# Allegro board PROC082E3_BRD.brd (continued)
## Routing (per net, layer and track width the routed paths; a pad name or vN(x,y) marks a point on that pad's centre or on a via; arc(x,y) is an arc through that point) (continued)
VCC_1V1: length 15.3
  L6_SIG2 w0.381: TP33.1 11.96,24.65 v1(18.99,17.62)
  BOTTOM w0.254: R243.1 19.18,17.81 v1(18.99,17.62)
  vias: v1(7.32,34.16) v1(7.32,33.27) v1(7.32,32.38) v1(7.57,29.54) v1(7.57,28.65) v1(8.2,34.16) v1(8.2,33.27) v1(8.2,32.38) v1(8.46,29.54) v1(8.46,28.65) v1(26.83,142.2) v1(26.86,142.88) v1(27.75,142.88) v1(27.72,142.2) v1(28.64,142.88) v1(28.61,142.2) v1(29.45,142.88) v1(29.42,142.2)
VCC_1V1_CBOOT: length 2.1
  TOP w0.254: v1(16,25.25) 15.84,25.09 C484.1
  BOTTOM w0.203: v1(16,25.25) 16.25,25 U33.13
VCC_1V1_COMP: length 2.5
  BOTTOM w0.254: C502.1 R244.1 U33.7
VCC_1V1_EN: length 1.9
  TOP w0.254: v1(17.45,25.15) 17.77,24.82 R197.2
  BOTTOM w0.203: v1(17.45,25.15) 17.25,24.94 U33.15
VCC_1V1_FB: length 3.1
  BOTTOM w0.254: U33.6 17.25,20.57 17.81,20.02 R239.1 R243.2
VCC_1V1_PG: length 1.9
  TOP w0.254: v1(16.75,25.17) 17.1,25.53 R245.1
  BOTTOM w0.203: U33.14 v1(16.75,25.17)
VCC_1V1_SW: length 1.4
  TOP w0.254: C484.2 14.86,24.97 14.63,25.2 v1(14.63,25.65)
VCC_1V8: length 12.8
  TOP w0.254: v1(17.81,72.7) 17.71,72.8 C473.1
  TOP w0.381: v1(37.9,161.59) 37.52,161.21 FL76.2 ; FL80.1 37.72,168.28 v1(37.82,168.17) ; FL78.2 v1(28.46,161.08)
  BOTTOM w0.254: v1(30.71,88.24) 30.81,88.24 31.06,88.49 U19.3
  BOTTOM w0.305: U22.2 18.21,74.45 18.42,74.24 C474.1 18.42,73.09 18.03,72.7 v1(17.81,72.7) ; U22.6 16.21,75.14 C243.1 v1(15.52,73.69)
  BOTTOM w0.381: R228.1 30.05,159.47 v1(30.05,159.31) ; R234.1 v1(33.58,160.24) ; R223.1 v1(34.74,170.38)
  vias: v1(22.13,138.37) v1(23.28,138.37) v1(23.96,91.58) v1(23.96,90.56) v1(23.96,89.54) v1(23.96,88.53) v1(24.98,91.58) v1(24.98,90.56) v1(24.98,89.54) v1(24.98,88.53)
VCC_1V8_EN: length 1.3
  BOTTOM w0.254: U19.1 R145.1
VCC_1V8_SW: length 6.3
  BOTTOM w0.229: 31.56,90.84 U19.5
  BOTTOM w0.381: 31.56,91.11 31.56,90.84
  BOTTOM w0.635: L29.1 31.56,91.11
VCC_3V3:
  vias: v1(41.64,40.22) v1(41.67,41.56) v1(41.67,40.88) v1(42.48,41.59) v1(42.48,40.9) v1(42.45,40.24) v1(44.99,92.95) v1(44.99,91.93) v1(46.01,92.95) v1(46.01,91.93) v1(47.47,92.85)
VCC_12V: length 46.5
  TOP w0.254: v1(73.44,30.99) 75.63,30.99 TP56.1
  TOP w0.305: R258.1 53.84,7.3 C526.1
  TOP w0.381: v1(54.53,9.65) C526.1
  L03_SIG1 w0.381: v1(54.53,9.65) 54.53,12.27 50.67,16.13 v1(50.67,17.65)
  L6_SIG2 w0.381: 41.66,17.91 41.27,17.53 34.47,17.53 v1(33.6,16.66)
  BOTTOM w0.203: U4.9 74.04,164.95 73.86,165.13
  BOTTOM w0.305: R253.1 v1(33.6,16.66) ; U27.9 73.83,28.81 73.53,29.11 ; U26.9 73.77,47.66 73.53,47.9 ; U28.4 42.43,21.36 42.59,21.21 C344.1 ; 76.56,166.7 76.72,166.53 U4.13 ; U7.9 9.25,139.08 v1(9.51,138.82) ; U12.9 9.15,118.15 9.41,117.89 9.89,117.89 ; U18.9 74.06,86.42 73.84,86.64 ; U3.9 9.79,162.55 ; U8.9 74.09,145.32 73.69,145.72 ; 73.46,67.36 73.71,67.11 U23.9 ; 9.41,96.22 9.15,96.48 U16.9 ; U17.9 73.9,105.73 73.63,105.99 ; U13.9 73.65,125.28 73.41,125.53
  vias: v1(9.39,94.88) v1(9.41,94.19) v1(9.51,160.26) v1(9.51,137.8) v1(9.51,136.79) v1(9.89,116.88) v1(9.89,115.86) v1(10.53,161.27) v1(10.53,160.26) v1(10.53,138.82) v1(10.53,137.8) v1(10.53,136.79) v1(10.91,116.88) v1(10.91,115.86) v1(11.54,137.8) v1(11.54,136.79) v1(42.42,20.19) v1(43.31,20.19) v1(43.94,21.08) v1(44.2,20.19) v1(45.09,20.19) v1(46.23,21.34) v1(46.23,20.45) v1(46.23,19.56) v1(46.23,18.67) v1(47.12,21.34) v1(47.12,20.45) v1(47.12,19.56) v1(47.12,18.67) v1(48.01,21.34) v1(48.01,20.45) v1(48.01,19.56) v1(48.01,18.67) v1(48.9,21.34) v1(48.9,20.45) v1(48.9,19.56) v1(48.9,18.67) v1(49.78,21.34) v1(49.78,20.45) v1(49.78,19.56) v1(49.78,18.67) v1(50.67,21.34) v1(50.67,20.45) v1(50.67,19.56) v1(50.67,18.67) v1(71.41,69.29) v1(71.41,68.28) v1(71.41,67.26) v1(71.81,51.09) v1(71.81,50.07) v1(71.96,167.82) v1(71.96,167.06) v1(71.96,166.3) v1(71.96,165.53) v1(71.96,148.31) v1(71.96,147.55) v1(71.96,146.79) v1(71.96,146.03) v1(71.99,128.73) v1(71.99,127.97) v1(71.99,127.2) v1(71.99,126.44) v1(72.04,109.26) v1(72.04,108.5) v1(72.04,107.74) v1(72.04,106.97) v1(72.42,88.6) v1(72.42,87.58) v1(72.42,86.56) v1(72.42,69.29) v1(72.42,68.28) v1(72.42,67.26) v1(72.42,30.99) v1(72.42,29.97) v1(72.83,51.09) v1(72.83,50.07) v1(72.98,167.82) v1(72.98,167.06) v1(72.98,166.3) v1(72.98,165.53) v1(72.98,148.31) v1(72.98,147.55) v1(72.98,146.79) v1(72.98,146.03) v1(73.01,128.73) v1(73.01,127.97) v1(73.01,127.2) v1(73.01,126.44) v1(73.06,109.26) v1(73.06,108.5) v1(73.06,107.74) v1(73.06,106.97) v1(73.06,88.6) v1(73.06,87.58) v1(73.06,86.56) v1(73.44,69.29) v1(73.44,68.28) v1(73.44,29.97) v1(73.69,88.6) v1(73.69,87.58)
VCC_12V/20V_HDR:
  vias: v1(21.59,11.81) v1(21.59,10.79) v1(21.59,9.78) v1(21.59,6.99) v1(21.59,5.97) v1(22.61,11.81) v1(22.61,10.79) v1(22.61,9.78) v1(22.61,6.99) v1(22.61,5.97) v1(23.62,11.81) v1(23.62,10.79) v1(23.62,9.78) v1(23.62,6.99) v1(23.62,5.97)
VCC_12V_EXP_CONN:
  vias: v1(53.85,23.88) v1(54.74,23.88) v1(55.63,24.38) v1(55.63,23.62) v1(56.13,25.15) v1(56.26,24.38) v1(56.39,23.62) v1(56.77,25.15) v1(56.9,24.38) v1(57.15,23.62) v1(57.66,24.26) v1(58.04,23.62) v1(58.42,24.26) v1(59.01,80.15) v1(59.01,79.26) v1(59.01,78.37) v1(59.01,77.47) v1(59.44,76.71) v1(59.9,80.15) v1(59.9,79.26) v1(59.9,78.37) v1(59.9,77.48) v1(60.33,76.71) v1(71.25,11.68) v1(71.25,10.79) v1(71.25,9.91) v1(71.25,9.02) v1(72.14,11.68) v1(72.14,10.79) v1(72.14,9.91) v1(72.14,9.02) v1(73.03,11.68) v1(73.03,10.79) v1(73.03,9.91) v1(73.03,9.02) v1(73.91,11.68) v1(73.91,10.79) v1(73.91,9.91) v1(73.91,9.02) v1(74.8,11.68) v1(74.8,10.79) v1(74.8,9.91) v1(74.8,9.02) v1(75.69,11.68) v1(75.69,10.79) v1(75.69,9.91) v1(75.69,9.02) v1(76.58,11.68) v1(76.58,10.79) v1(76.58,9.91) v1(76.58,9.02) v1(77.47,11.68) v1(78.36,11.68)
VCC_CSI_IO: length 220.2
  TOP w0.381: v1(39.7,117.88) 39.7,116.18 39.22,115.7 C195.1 38.67,115.17 v1(38.28,115.56) 36.78,114.06 36.78,103.86 35.43,102.51 35.43,94.46 36.8,93.09 v1(36.8,89.08) 38.51,89.08 40.34,90.92 v1(41.07,90.92) v1(42.45,90.92) ; R197.1 18.75,24.35 19.13,24.72 v1(19.13,25.63) ; C309.1 22.8,54.39 v1(23.96,54.39) ; R17.1 25.9,122.58 v1(26.6,121.88) ; v1(26.85,31.62) 26.74,31.51 R209.1 ; R206.1 v1(47.5,105.83) ; 51.44,52.58 51.44,42.92 52.28,42.07 R46.1 R47.1 ; R212.1 v1(16.17,33.46)
  L03_SIG1 w0.381: 20.36,51.01 19.24,51.01 18.49,51.76 18.49,58.91 23.27,63.69 23.27,68.28 v1(22.1,69.45) ; 20.36,51.01 20.93,50.44 v1(20.93,47.09) 20.93,46.23 19.84,45.14 19.84,37.13 ; 20.36,51.01 20.36,51.54 23.2,54.39 v1(23.96,54.39) 24.54,54.97 v1(24.54,57.24) ; v1(39.7,117.88) 39.7,116.13 41.2,114.63 41.2,112.93 41.86,112.27 42.47,112.27 42.98,111.76 46.25,111.76 46.96,111.06 46.96,106.37 v1(47.5,105.83) ; 19.84,37.13 20.63,36.33 20.63,33.95 22.57,32 26.47,32 v1(26.85,31.62) ; 19.84,37.13 v1(16.17,33.46) 16.17,28.59 v1(19.13,25.63) ; v1(26.6,121.88) 27.44,121.04 36.68,121.04 37.57,121.93 37.57,126.15 36.97,126.75 v1(36.45,126.75) ; v1(10.3,94.19) 11.47,93.02 v1(15.11,93.02)
  BOTTOM w0.254: R145.2 35.44,87.71 v1(36.8,89.08)
  BOTTOM w0.305: U9.16 37.88,115.16 v1(38.28,115.56) ; U24.16 38.83,57.8 38.23,57.21 C302.1 v1(38.94,56.59) ; U25.16 21.67,54.94 22.22,54.39 C310.1
  BOTTOM w0.381: R170.2 22.08,68.66 R172.2 v1(22.1,69.45) ; v1(6.36,74.59) 6.73,74.59 7.11,74.97 FL60.1 v1(6.35,75.44) ; R149.1 v1(10.3,94.19) ; R180.2 v1(41.13,55.11) ; v1(38.28,115.56) 38.34,115.62 C191.1 ; v1(23.96,54.39) C310.1 ; v1(36.45,126.75) 37.53,127.82 R87.2 R86.2 39.86,128.17 42.73,128.17 42.91,128.35 44.78,128.35 45.82,127.31 45.82,119.59 44.11,117.88 v1(39.7,117.88) R99.2 ; U20.8 C241.1 v1(7.94,85.74) ; v1(15.11,93.02) 14.68,93.45 R146.1 ; v1(13.19,84.05) 12.79,84.05 R153.1 ; R176.2 R179.2 v1(51.14,56.83) ; v1(6.78,89.1) 6.78,89.94 7.38,90.54 R151.1 ; R178.2 v1(24.54,57.24)
  vias: v1(41.01,89.91) v1(41.83,91.89)
VDD1V8_P_HUB1: length 2.5
  BOTTOM w0.229: 25.07,110.92 25.65,110.92 25.82,111.09 U9.44
  BOTTOM w0.381: 25.07,110.92 24.84,110.68 C206.1 v1(24.84,109.62)
VDD1V8_P_HUB2: length 3.6
  TOP w0.381: v1(33.78,71.43) 33.72,71.38 C83.1
  BOTTOM w0.305: C85.1 34.77,70.84 35.08,70.54 U24.44
  BOTTOM w0.381: C85.1 v1(33.78,71.43)
VDD1V8_P_HUB3: length 4.5
  TOP w0.381: C109.1 8.02,49.56 v1(8.06,49.6) 8.08,49.58 C91.1
  BOTTOM w0.305: U25.44 9.85,50.64 9.63,50.42 9.25,50.42
  BOTTOM w0.381: 9.25,50.42 8.86,50.04 8.86,49.61 8.87,49.6 ; C89.1 8.87,49.6 ; 8.87,49.6 v1(8.06,49.6)
VDD11_CSI_HUB1: length 13
  TOP w0.254: 22.08,118.74 C463.1
  TOP w0.381: C459.1 23.12,113.15 v1(23.01,113.26) 22.95,113.32 22.95,114.17 C466.1 ; v1(25.59,110.09) 26.27,110.09 C460.1 C465.1 ; C462.1 23.18,118.75 22.65,118.75 v1(22.64,118.74) 22.08,118.74
  BOTTOM w0.229: U9.43 26.32,110.81 26.26,110.74 ; U9.30 32.82,110.5
  BOTTOM w0.305: 23.85,113.21 24.4,112.66 U9.46 ; C186.1 23.94,118.74 24.36,119.16 U9.59
  BOTTOM w0.381: 26.26,110.74 26.26,110.11 C205.1 v1(25.59,110.09) ; 23.85,113.21 23.85,113.21 C196.1 23.64,113.26 v1(23.01,113.26) ; v1(22.64,118.74) C186.1
  vias: v1(21.28,147.71) v1(21.3,146.99) v1(22.12,147.71) v1(22.14,146.99) v1(32.98,107.98) v1(33.1,109.35)
VDD11_CSI_HUB2: length 21.7
  TOP w0.381: v1(37.6,71.86) 37.64,71.83 C436.1 ; C438.1 C255.1 31.9,62.69 v1(31.91,62.7) ; v1(33.78,70.03) 33.84,69.96 C431.1 33.85,69.41 C435.1 ; C434.1 33.68,62.99 v1(33.38,62.7) 33.32,62.64 C322.1 ; C433.1 40.88,71.49 v1(41.51,71.49) 41.74,71.26 C437.1
  BOTTOM w0.254: U24.46 36.33,70.94 36.59,71.2 ; 42.68,71.08 42.83,70.93 U24.59
  BOTTOM w0.305: C263.1 34.05,69.07 U24.43 ; U24.30 34.45,62.57 34.2,62.32 34.44,62.07 U24.29
  BOTTOM w0.381: 36.59,71.2 36.93,71.54 C256.1 37.47,72 v1(37.6,71.86) 38.38,71.86 C432.1 ; v1(31.91,62.7) C102.1 C290.1 ; 42.68,71.08 42.27,71.49 C291.1 v1(41.51,71.49) ; 34.2,62.32 34.15,62.32 33.74,61.91 C290.1 ; C290.1 v1(33.38,62.7) ; v1(33.78,70.03) C263.1
  vias: v1(29.02,47.99) v1(29.02,47.1) v1(29.02,46.21) v1(30.03,47.99) v1(30.03,47.1) v1(30.03,46.21)
VDD11_CSI_HUB3: length 16
  TOP w0.381: C413.1 7.62,54.86 v1(7.62,54.07) 7.63,54.05 C420.1 ; C416.1 C419.1 9.78,49.51 v1(9.66,49.63) ; C325.1 7.27,57.97 v1(7.66,57.58) 7.28,57.2 C300.1
  BOTTOM w0.229: U25.43 10.35,50.38 10.32,50.36 ; U25.30 16.85,50.5 17.35,50
  BOTTOM w0.305: U25.59 8.46,58.94 7.69,58.16 C110.1 ; U25.29 17.35,50 17.75,49.59 ; v1(9.66,49.63) C319.1 ; C311.1 7.96,53.33 8.27,53.02 8.27,52.74 8.57,52.44 U25.46
  BOTTOM w0.381: C110.1 7.2,58.04 v1(7.66,57.58) ; 10.32,50.36 C319.1 ; C311.1 v1(7.62,54.07)
  vias: v1(8.41,45.19) v1(8.41,44.17) v1(9.42,45.19) v1(9.42,44.17) v1(17.68,48.14) v1(17.69,47.52)
VDD11_FPD_HUB1: length 7.3
  TOP w0.381: C457.1 34.51,123.2 C22.1 34.48,124.24 v1(33.82,124.24) 33.24,124.24 C172.1 ; C456.1 28.31,126.15 v1(28.32,126.17) C149.1
  BOTTOM w0.305: U9.83 v1(33.82,124.24) ; 28.32,125.44 U9.72
  BOTTOM w0.381: 28.32,125.44 C174.1 v1(28.32,126.17)
  vias: v1(22.64,143.21) v1(22.64,142.55) v1(23.43,143.21) v1(23.43,142.55)
VDD11_FPD_HUB2: length 18.6
  TOP w0.381: C326.1 49.69,66.91 v1(49.67,66.89) 49,66.89 C272.1 ; C442.1 C441.1 48.06,61.51 v1(48,61.57) C103.1
  L03_SIG1 w0.508: v1(49.67,66.89) 47.59,66.89 47.08,66.39 47.08,63.32 48,62.41 v1(48,61.57)
  L04_PWR1 w0.508: v1(49.67,66.89) 46.84,66.89
  BOTTOM w0.305: 48.46,67.07 U24.72 ; U24.83 v1(48,61.57)
  BOTTOM w0.381: 48.46,67.07 48.65,66.88 C273.1 49.03,66.89 v1(49.67,66.89)
  vias: v1(28.74,43.42) v1(28.74,42.66) v1(28.74,41.77) v1(29.75,43.42) v1(29.75,42.66) v1(29.75,41.77)
VDD11_FPD_HUB3: length 8.4
  TOP w0.381: C421.1 11.93,65.6 v1(11.76,65.43) 11.93,65.26 C422.1 ; v1(17.29,64.91) C324.1 C95.1
  BOTTOM w0.305: C324.1 17.85,64.35 U25.83 ; 12.35,64.26 U25.72
  BOTTOM w0.381: v1(17.29,64.91) C324.1 ; v1(11.76,65.43) C97.1 12.32,64.29 12.35,64.26
  vias: v1(14.23,43.6) v1(14.31,44.38) v1(15.33,44.38)
VDD11_L_HUB1: length 7.3
  TOP w0.381: C145.1 23.37,120.97 v1(23.13,121.21) ; C469.1 39.3,118.64 v1(39.3,119.36)
  BOTTOM w0.229: U9.62 24.53,120.66 ; U9.5 37.65,120.66
  BOTTOM w0.381: v1(23.13,121.21) 23.32,121.02 C183.1 23.87,120.54 23.98,120.66 24.53,120.66 ; 37.65,120.66 38,120.66 38.64,120.02 C185.1 39.39,119.44 v1(39.3,119.36)
  vias: v1(30.85,148.27) v1(30.85,147.38) v1(31.74,148.27) v1(31.74,147.38)
VDD11_L_HUB2: length 50.4
  TOP w0.381: C332.1 v1(44.36,71.75) ; C440.1 44.79,56.07 v1(45,56.27)
  L03_SIG1 w0.762: v1(29.75,38.39) 32.31,38.39 34.88,40.96 34.88,49.03 37.04,51.2 40.78,51.2 44.94,55.36 44.94,56.22 v1(45,56.27) 44.65,56.62 44.65,67.69 44.12,68.22 44.12,71.5 v1(44.36,71.75)
  BOTTOM w0.254: C254.1 43.76,71.42 44.33,70.85 U24.62
  BOTTOM w0.305: C301.1 44.22,56.79 44.33,56.9 U24.5
  BOTTOM w0.381: C301.1 v1(45,56.27) ; v1(44.36,71.75) C254.1
  vias: v1(28.74,39.4) v1(28.74,38.39) v1(28.74,37.37) v1(29.75,39.4) v1(29.75,37.37)
VDD11_L_HUB3: length 6.7
  TOP w0.381: C411.1 7.31,59.71 v1(7.2,59.6) ; v1(22.9,61.1) 22.92,61.07 C342.1
  BOTTOM w0.229: 8.46,60.44 U25.62
  BOTTOM w0.305: C295.1 22.82,60.44 U25.5
  BOTTOM w0.381: 8.46,60.44 8.03,60.44 7.86,60.27 C293.1 v1(7.2,59.6) ; C295.1 v1(22.9,61.1)
  vias: v1(19.23,45.24) v1(19.23,44.23) v1(19.23,43.21)
VDD11_P0_HUB1: length 4.3
  TOP w0.381: C203.1 23.38,111.07 v1(23.38,111.23) 23.85,111.7 C141.1
  BOTTOM w0.305: 24.22,112.16 U9.45
  BOTTOM w0.381: 24.22,112.16 24.11,112.05 C177.1 23.34,111.28 v1(23.38,111.23)
  vias: v1(30.53,151.08) v1(30.53,150.44) v1(31.17,151.08) v1(31.17,150.44)
VDD11_P0_HUB2: length 3.8
  TOP w0.381: C82.1 v1(36.08,71.97) 36.09,71.98 C317.1
  BOTTOM w0.254: U24.45 35.83,70.85 35.69,70.99
  BOTTOM w0.381: 35.69,70.99 35.42,71.26 C82.1 v1(36.08,71.97)
  vias: v1(28.91,51.82) v1(28.91,50.8) v1(29.92,51.82) v1(29.92,50.8)
VDD11_P0_HUB3: length 4
  TOP w0.381: C313.1 C331.1 7.65,52.55 v1(7.63,52.58)
  BOTTOM w0.229: U25.45 8.26,51.94
  BOTTOM w0.381: 8.26,51.94 7.63,51.94 C279.1 7.61,51.95 7.61,52.56 v1(7.63,52.58)
  vias: v1(4.47,36.7) v1(4.47,35.69) v1(5.49,36.7) v1(5.49,35.69)
VDD11_P1_HUB1: length 6.8
  TOP w0.381: v1(32.05,124.92) C369.1 31.08,124.81 29.48,124.81 C371.1 FL70.2
  BOTTOM w0.305: U9.78 C370.1
  BOTTOM w0.381: v1(32.05,124.92) C370.1
VDD11_P1_HUB2: length 0.9
  BOTTOM w0.305: U24.78 v1(46.19,64.07)
VDD11_P1_HUB3: length 4.8
  TOP w0.381: C372.1 15.72,64.91 v1(15.09,64.91) 14.95,65.05 C374.1
  TOP w0.508: FL71.2 v1(4.47,53.04)
  BOTTOM w0.305: C373.1 15.76,64.56 15.35,64.15 U25.78
  BOTTOM w0.381: C373.1 v1(15.09,64.91)
VDD18_FPD_HUB1: length 21
  TOP w0.381: v1(35.75,121.79) 34.8,121.79 C175.1 33.5,121.76 C452.1 32.99,121.77 32.85,121.62 C29.1 32.36,122.25 v1(32.4,122.29) ; v1(36.48,125.02) C24.1 37.29,124.91 C455.1 ; C453.1 28.56,121.87 C28.1 29.64,122.36 v1(29.82,122.54) 29.82,122.99 30.21,123.38 C451.1 ; R15.1 23.5,124.06 v1(23.16,123.72) ; C454.1 26.78,126.09 26.69,126.01 v1(26.69,125.82) 26.77,125.74 C450.1 ; v1(33.79,126.43) 33.38,126.43 32.76,127.05 R13.1
  BOTTOM w0.305: v1(29.82,122.54) U9.75 ; v1(32.4,122.29) 32.32,122.36 U9.80 ; 35.32,124.43 U9.86 ; 26.82,124.47 U9.69
  BOTTOM w0.381: 35.32,124.43 35.79,124.89 C173.1 36.37,125.13 v1(36.48,125.02) ; 26.82,124.47 26.69,124.61 C23.1 v1(26.69,125.82)
  vias: v1(23.67,130.5) v1(25.06,130.5)
VDD18_FPD_HUB2: length 25.2
  TOP w0.381: v1(48.8,64.58) 49.41,64.58 C96.1 50.04,64.54 51.27,64.54 C448.1 ; C447.1 49.59,60.07 v1(49.53,60.01) 49.47,60.07 C445.1 ; v1(48.8,63.91) 50.02,63.91 50.09,63.98 51.1,63.98 C444.1 C449.1 ; R38.1 52.45,70.75 R37.1 52.35,69.76 51.89,69.29 C446.1 v1(49.66,69.29) C86.1
  BOTTOM w0.254: v1(49.53,60.01) 48.91,60.01 C296.1 48.2,59.94 48.07,60.07 U24.86
  BOTTOM w0.305: C287.1 48.24,63.3 48.02,63.07 U24.80 ; U24.75 47.78,65.57 48.25,65.11 C280.1 ; U24.69 47.66,68.57 48.38,69.29 C86.1 v1(49.66,69.29)
  BOTTOM w0.381: C280.1 v1(48.8,64.58) ; C287.1 v1(48.8,63.91)
  vias: v1(35.72,75.68) v1(35.72,74.41)
VDD18_FPD_HUB3: length 19.3
  TOP w0.381: v1(16.16,64.05) 16.31,63.9 C99.1 16.99,63.87 C424.1 C429.1 ; v1(14.63,64.31) 14.45,64.13 C426.1 13.77,63.25 C427.1 ; C425.1 9.22,64.88 v1(9.15,64.81) 8.87,64.53 C98.1 ; v1(10.9,62.11) 11.58,61.43 R171.1 ; v1(20.75,64.95) 20.83,64.87 C94.1 C428.1
  BOTTOM w0.229: 10.67,64.26 10.85,64.08 U25.69
  BOTTOM w0.305: U25.75 13.85,64.29 C101.1 14.53,64.42 v1(14.63,64.31) ; C275.1 19.35,64.34 U25.86 ; U25.80 16.35,63.86 v1(16.16,64.05)
  BOTTOM w0.381: v1(20.75,64.95) C275.1 ; v1(9.15,64.81) C282.1 10.12,64.81 10.67,64.26
  vias: v1(21.71,63.58) v1(22.45,66.92)
VDD_1P1_D: length 4.5
  TOP w0.381: C390.1 27.29,165.05 v1(27.51,164.82) 27.29,164.6 C470.1
  BOTTOM w0.254: v1(27.51,164.82) 27.51,164.54 27.54,164.52 C399.1 28.32,164.08 28.55,164.31 U32.26
VDD_1P1_DRV: length 4
  TOP w0.381: C471.1 v1(36.14,164.41) 36.09,164.36 C382.1
  BOTTOM w0.229: U32.15 35.03,164.31 35.26,164.08
  BOTTOM w0.381: 35.26,164.08 35.28,164.08 35.54,163.83 C381.1 v1(36.14,164.41)
VDD_1P1_PLL: length 5
  TOP w0.381: C472.1 v1(36.03,169.61)
  BOTTOM w0.305: U32.10 34.98,166.81 35.36,167.19 35.36,167.31
  BOTTOM w0.381: v1(36.03,169.61) C385.1 36.03,168.27 36.14,168.16 C386.1 35.8,167.75 35.36,167.31
VDD_1P8_D: length 5
  TOP w0.381: FL78.1 v1(27.54,161.08)
  BOTTOM w0.254: U32.25 29.04,163.81 28.85,163.63
  BOTTOM w0.381: 28.85,163.63 28.3,163.07 C400.1 FL78.1 v1(27.54,161.08)
VDD_1P8_DRV: length 4.5
  TOP w0.381: C387.1 36.14,162.63 v1(36.14,162) 36.14,161.25 FL76.1
  BOTTOM w0.305: U32.16 34.79,163.81 35,163.6 35,163.22
  BOTTOM w0.381: v1(36.14,162) 36.14,162 C398.1 35.56,162.66 35,163.22
VDD_1P8_PLL: length 6.4
  TOP w0.381: FL80.2 C384.1 ; C384.1 35.52,167 35.18,166.67 C408.2 ; C384.1 v1(36.14,166.19)
  BOTTOM w0.305: 35.71,166.78 35.25,166.31 U32.11
  BOTTOM w0.381: 35.71,166.78 C383.1 v1(36.14,166.19)
VDD_1V1_HUB1: length 33.1
  TOP w0.254: R208.1 44.32,109.19 43.86,108.73 43.86,108.7 43.7,108.53 U29.9
  TOP w0.381: v1(28.07,122.3) 27.71,122.66 FL70.1
  L03_SIG1 w0.381: v1(43.21,111.23) 42.72,110.74 41.86,110.74 41.43,111.18 39.7,111.18 39.04,111.84 29.69,111.84 27.73,113.79 27.73,117.45 25.83,119.35 25.83,121.92 26.58,122.67 27.7,122.67 v1(28.07,122.3)
  BOTTOM w0.254: TP51.1 43.15,110.62 43.21,110.67 v1(43.21,111.23)
VDD_1V1_HUB1_EN: length 1.6
  TOP w0.254: U29.5 R206.2
VDD_1V1_HUB1_FB: length 4.8
  TOP w0.203: R207.1 45.72,109.19 ; 45.72,109.19 45.72,108.86 45.47,108.61 44.75,108.61 44.2,108.05 U29.8 ; 45.72,109.19 45.11,109.19 45.01,109.3 45.01,109.93 44.77,110.17 R208.2
VDD_1V1_HUB1_PG: length 2.2
  TOP w0.254: U29.3 v1(44.2,103.92)
  BOTTOM w0.381: TP38.1 44.23,103.95 v1(44.2,103.92)
VDD_1V1_HUB1_SS: length 3.2
  TOP w0.203: U29.7 44.7,107.99 44.96,108.25 46.3,108.25 46.78,108.74 C363.1
VDD_1V1_HUB2: length 61.6
  TOP w0.508: FL69.1 46.02,72.64 43.84,74.83 40.72,74.83 39.89,74 39.89,71.59 37.52,69.22 37.52,58.5 v1(33.67,54.65) 31.29,52.27 31.29,50.5 29.57,48.77 27.79,48.77 20.36,41.34 C513.1
  BOTTOM w0.381: v1(33.67,54.65) 33.67,54.6 TP52.1
VDD_1V1_HUB2_EN: length 1.6
  TOP w0.203: U30.5 26.06,29.94 26.19,30.07 R209.2
VDD_1V1_HUB2_FB: length 3.5
  TOP w0.203: U30.8 24.23,33.17 24.63,33.57 R210.1 24.16,33.93 23.93,34.16 23.93,34.65 23.62,34.95 R211.2
VDD_1V1_HUB2_PG: length 9.7
  TOP w0.203: U30.3 v1(24.23,29.36)
  L6_SIG2 w0.254: v1(21.29,36.5) 22.66,35.13 22.66,30.94 v1(24.23,29.36)
  BOTTOM w0.203: v1(21.29,36.5) 21.29,36.47 TP39.1
VDD_1V1_HUB2_SS: length 1.9
  TOP w0.203: C364.1 25.65,33.55 25.45,33.35 24.94,33.35 24.73,33.14 U30.7
VDD_1V1_HUB3: length 23
  TOP w0.508: R214.1 10.89,35.33 10.85,35.28 C519.1 9.22,35.28 8.71,35.79 8.71,37.64 v1(4.47,41.88) FL71.1
  BOTTOM w0.508: v1(4.47,41.88) 5.33,41.02 TP53.1
VDD_1V1_HUB3_EN: length 1.6
  TOP w0.203: R212.2 15.11,31.24 14.98,31.11 U31.5
VDD_1V1_HUB3_FB: length 3.7
  TOP w0.254: R214.2 13.19,36.31 13.31,36.2 13.31,35.59 13.56,35.33 13.96,35.33 R213.1 13.96,34.84 13.67,34.54 U31.8
VDD_1V1_HUB3_PG: length 13.1
  TOP w0.203: v1(13.67,30.53) U31.3
  L6_SIG2 w0.203: v1(13.67,30.53) 13.67,29.34 11.38,27.05 5.61,27.05 v1(4.42,28.24)
  BOTTOM w0.203: TP40.1 v1(4.42,28.24)
VDD_1V1_HUB3_SS: length 2
  TOP w0.254: U31.7 14.17,34.31 14.45,34.59 14.78,34.59 14.98,34.79 C365.1
VDD_3V3: length 4.1
  TOP w0.381: v1(14.64,76.59) 14.64,75.87 C75.1 ; v1(20.97,76.77) 20.92,76.72 C72.1
  BOTTOM w0.305: v1(14.64,76.59) 14.82,76.77 U22.8 ; U22.23 v1(20.97,76.77)
  vias: v1(36.96,94.92) v1(37.97,94.92)
971_GPIO0_TP: length 7.5
  BOTTOM w0.152: TP42.1 37.5,159.54 35.81,159.54 35.1,160.25 35.1,160.78 33.68,162.21 U32.17
971_GPIO1_TP: length 5.7
  BOTTOM w0.152: TP43.1 34.7,159.97 34.7,160.71 33.18,162.22 U32.18
971_GPIO2_TP: length 4.4
  BOTTOM w0.152: U32.27 28.13,164.81 26.59,166.34 TP44.1
971_GPIO3_TP: length 5.6
  BOTTOM w0.152: U32.28 28.12,165.31 25.65,167.78 TP45.1
971_IDX/CLK_OUT: length 6.4
  TOP w0.152: R232.1 v1(33.55,161.11)
  BOTTOM w0.152: U32.19 32.68,162.11 32.8,161.99 R234.2 33.45,161.22 v1(33.55,161.11) 34.13,160.53 34.13,159.07 TP41.1
971_MODE: length 3.7
  TOP w0.152: R233.1 v1(30.07,161.21)
  BOTTOM w0.152: v1(30.07,161.21) R228.2 30.85,161.21 31.24,161.6 31.24,161.77 31.68,162.21 U32.21
971_PDB: length 3.2
  TOP w0.152: v1(33.76,170.42) 33.76,169.73 C409.1
  BOTTOM w0.152: v1(33.76,170.42) R223.2 33.76,169.11 33.68,169.03 U32.8
971_REF CLK: length 108.5
  TOP w0.152: R230.2 20.37,79.15 v1(19.82,79.7)
  L6_SIG2 w0.102: v1(23.92,125.18) 23.81,125.18 22.43,123.8 22.43,120.72 21.38,119.67 21.38,112.37 21.95,111.8 21.95,106.35 21.59,105.99 21.59,95.33 19.96,93.71 19.96,93.22 17.19,90.44 14.79,90.44 12.26,87.91 12.26,87.26 12.84,86.68 15.5,86.68 17.45,84.72 18.65,84.72 21.06,82.31 21.06,80.93 v1(19.82,79.7)
  BOTTOM w0.152: v1(23.92,125.18) 24.18,125.44 24.18,127.86 22.3,129.74 20.19,129.74 17.97,131.96 17.97,149.64 22.99,154.66 28.71,154.66 31.81,157.75 R236.1
971_REF CLK_R: length 5.5
  TOP w0.152: R230.1 18.52,78.13 18.01,77.62 18.01,74.99 v1(17.71,74.7)
  BOTTOM w0.152: U22.3 v1(17.71,74.7)
C_CAM5_RIN0_N: length 20.9
  TOP w0.13: R33.2 71.41,75.89 71.28,76.01 64.81,76.01 arc(63.38,75.73) 62.17,74.92 57.55,70.3 arc(57.16,70.04) 56.71,69.95 55.9,69.95 v1(55.65,69.7)
  BOTTOM w0.13: v1(55.65,69.7) 55.57,69.79 arc(55.38,69.91) 55.16,69.95 54.23,69.95 arc(53.87,69.88) 53.57,69.68 C262.1
C_CAM5_RIN0_P: length 27.7
  TOP w0.13: 71.41,76.42 64.81,76.42 arc(63.22,76.11) 61.88,75.21 57.26,70.59 arc(57.01,70.42) 56.71,70.36 55.9,70.36 v1(55.65,70.61)
  TOP w0.445: 71.41,76.58 J15.1
  BOTTOM w0.13: C260.1 53.57,70.64 arc(53.87,70.43) 54.23,70.36 55.16,70.36 arc(55.38,70.41) 55.57,70.53 v1(55.65,70.61)
C_CAM6_RIN1_N: length 26.3
  TOP w0.13: R44.2 71.41,56.33 71.28,56.46 61.77,56.46 arc(60.01,57.18) 59.28,58.94 59.28,64.63 arc(58.99,65.32) 58.3,65.61 58.29,65.61 arc(58.24,65.6) 58.2,65.57 v1(57.98,65.35)
  BOTTOM w0.13: C281.1 53.63,65.35 arc(53.91,65.54) 54.24,65.61 57.68,65.61 arc(57.73,65.6) 57.77,65.57 v1(57.98,65.35)
C_CAM6_RIN1_P: length 33.1
  TOP w0.13: v1(57.98,66.27) 58.2,66.05 arc(58.24,66.03) 58.29,66.02 58.3,66.02 arc(59.28,65.61) 59.69,64.63 59.69,58.94 arc(60.3,57.47) 61.77,56.87 71.41,56.87
  TOP w0.445: 71.41,57.02 J16.1
  BOTTOM w0.13: v1(57.98,66.27) 57.77,66.05 arc(57.73,66.03) 57.68,66.02 54.24,66.02 arc(53.91,66.08) 53.63,66.27 C274.1
C_CAM7_RIN2_N: length 39.2
  TOP w0.13: v1(55.04,62.46) 55.25,62.67 arc(55.29,62.7) 55.34,62.71 56.38,62.71 arc(57.29,62.33) 57.66,61.43 57.66,50.42 arc(57.83,49.58) 58.32,48.86 60.86,46.31 arc(60.97,46.19) 61.07,46.06 arc(61.35,45.5) 61.45,44.89 61.45,41.68 arc(61.69,40.48) 62.37,39.46 63.9,37.93 arc(65.04,37.17) 66.39,36.9 71.28,36.9 71.41,36.77 R48.2
  BOTTOM w0.13: v1(55.04,62.46) 54.82,62.67 arc(54.78,62.7) 54.73,62.71 54.11,62.71 arc(53.9,62.67) 53.72,62.54 C288.1
C_CAM7_RIN2_P: length 46
  TOP w0.13: v1(55.04,63.37) 55.25,63.16 arc(55.29,63.13) 55.34,63.12 56.38,63.12 arc(57.58,62.62) 58.07,61.43 58.07,50.42 arc(58.21,49.73) 58.6,49.14 61.15,46.6 arc(61.47,46.21) 61.7,45.76 arc(61.82,45.33) 61.86,44.89 61.86,41.68 arc(62.07,40.63) 62.66,39.75 64.19,38.22 arc(65.2,37.54) 66.39,37.31 71.41,37.31
  TOP w0.445: 71.41,37.47 J17.1
  BOTTOM w0.13: C285.1 53.72,63.28 arc(53.9,63.16) 54.11,63.12 54.73,63.12 arc(54.78,63.13) 54.82,63.16 v1(55.04,63.37)
C_CAM8_RIN3_N: length 53.7
  TOP w0.13: R50.2 71.41,17.21 71.28,17.34 68.54,17.34 arc(67.58,17.53) 66.77,18.08 61.06,23.78 arc(59.64,25.92) 59.13,28.43 59.13,43.96 arc(58.99,44.68) 58.59,45.28 56.78,47.09 arc(56.21,47.94) 56.01,48.96 56.01,59.4 arc(55.88,59.72) 55.56,59.85 55.34,59.85 arc(55.29,59.84) 55.25,59.81 v1(55.04,59.6)
  BOTTOM w0.13: v1(55.04,59.6) 54.93,59.7 arc(54.77,59.81) 54.57,59.85 54.11,59.85 arc(53.9,59.81) 53.72,59.68 C297.1
C_CAM8_RIN3_P: length 60.4
  TOP w0.13: v1(55.04,60.51) 55.25,60.3 arc(55.29,60.27) 55.34,60.26 55.56,60.26 arc(56.17,60.01) 56.42,59.4 56.42,48.96 arc(56.59,48.1) 57.07,47.38 58.88,45.57 arc(59.37,44.83) 59.54,43.96 59.54,28.43 arc(60.01,26.07) 61.35,24.07 67.06,18.36 arc(67.74,17.91) 68.54,17.75 71.41,17.75
  TOP w0.445: 71.41,17.91 J18.1
  BOTTOM w0.13: C292.1 53.72,60.42 arc(53.9,60.3) 54.11,60.26 54.57,60.26 arc(54.77,60.3) 54.93,60.41 v1(55.04,60.51)
C_CAM9_RIN0_N: length 46.4
  TOP w0.13: R26.2 10.92,106.99 11.05,106.87 15.05,106.87 arc(15.66,106.74) 16.18,106.4 16.39,106.18 arc(16.88,105.46) 17.05,104.61 17.05,87.45 arc(16.8,86.22) 16.1,85.17 11.27,80.34 arc(10.62,79.37) 10.39,78.22 10.39,70.88 arc(10.4,70.83) 10.43,70.79 v1(10.65,70.57)
  BOTTOM w0.13: C270.1 10.77,68.84 arc(10.54,69.18) 10.46,69.59 10.46,70.1 arc(10.51,70.36) v1(10.65,70.57)
C_CAM9_RIN0_P: length 52.5
  TOP w0.13: 10.92,106.46 15.05,106.46 arc(15.5,106.37) 15.89,106.11 16.11,105.89 arc(16.5,105.3) 16.64,104.61 16.64,87.45 arc(16.42,86.37) 15.81,85.46 10.98,80.63 arc(10.24,79.52) 9.98,78.22 9.98,70.86 arc(9.9,70.65) v1(9.69,70.57)
  TOP w0.445: J14.1 10.92,106.3
  BOTTOM w0.13: C271.1 9.74,68.84 arc(9.97,69.18) 10.05,69.59 10.05,70.57 arc(9.87,70.75) v1(9.69,70.57)
C_CAM10_RIN1_N: length 69.5
  TOP w0.13: v1(13.44,70.57) 13.2,70.81 arc(13.17,70.85) 13.16,70.9 13.16,71.32 arc(13.08,71.73) 12.85,72.08 arc(12.39,72.78) 12.22,73.59 12.22,77.58 arc(12.47,78.81) 13.17,79.85 17.35,84.04 arc(18.29,85.44) 18.62,87.1 18.62,108.92 arc(18.51,109.48) 18.19,109.96 18.02,110.15 arc(17.79,110.53) 17.71,110.96 17.71,126.6 arc(17.56,127.38) 17.12,128.04 16.78,128.37 arc(16.13,128.81) 15.35,128.96 11.05,128.96 10.92,129.09 R18.2
  BOTTOM w0.13: C268.1 13.39,69.01 arc(13.31,69.13) 13.28,69.27 13.28,70.35 arc(13.29,70.4) 13.32,70.44 v1(13.44,70.57)
C_CAM10_RIN1_P: length 75.5
  TOP w0.13: 10.92,128.55 15.35,128.55 arc(15.97,128.43) 16.5,128.08 16.83,127.75 arc(17.18,127.22) 17.3,126.6 17.3,110.96 arc(17.41,110.38) 17.71,109.88 17.89,109.68 17.9,109.67 arc(18.13,109.33) 18.21,108.92 18.21,87.1 arc(17.91,85.6) 17.06,84.32 12.88,80.14 arc(12.09,78.96) 11.81,77.58 11.81,73.59 arc(12.01,72.62) 12.56,71.8 arc(12.7,71.58) 12.76,71.32 12.76,70.71 arc(12.71,70.61) 12.61,70.57 v1(12.48,70.57)
  TOP w0.445: 10.92,128.4 J11.1
  BOTTOM w0.13: v1(12.48,70.57) 12.54,70.64 arc(12.75,70.68) 12.87,70.5 12.87,69.27 arc(12.87,69.27) 12.87,69.26 arc(12.86,69.18) 12.81,69.12 C269.1
C_CAM11_RIN2_N: length 94.6
  TOP w0.13: v1(17.03,70.57) 17.02,70.58 arc(16.85,70.82) 16.76,71.09 arc(16.75,71.16) 16.75,71.23 16.75,71.68 arc(16.39,72.54) 15.54,72.9 14.36,72.9 arc(13.79,73.14) 13.55,73.7 13.55,77.01 arc(13.57,77.1) 13.62,77.17 19.41,82.96 arc(20.07,83.94) 20.3,85.11 20.3,110.95 arc(20.15,111.69) 19.73,112.31 19.62,112.42 arc(19.42,112.72) 19.35,113.07 19.35,130.57 arc(19.14,131.64) 18.53,132.55 18.44,132.64 arc(18.12,133.12) 18.01,133.69 18.01,148.78 arc(17.86,149.53) 17.43,150.16 17.34,150.26 arc(16.45,150.85) 15.4,151.06 11.05,151.06 10.92,151.19 R7.2
  BOTTOM w0.13: v1(17.03,70.57) 16.79,70.33 arc(16.76,70.29) 16.75,70.24 16.75,69.31 arc(16.8,69.08) 16.92,68.89 C266.1
C_CAM11_RIN2_P: length 100.8
  TOP w0.13: 10.92,150.65 15.4,150.65 arc(16.29,150.48) 17.05,149.97 17.15,149.87 arc(17.48,149.37) 17.6,148.78 17.6,133.69 arc(17.74,132.96) 18.16,132.35 18.25,132.26 arc(18.76,131.48) 18.95,130.57 18.95,113.07 arc(19.05,112.56) 19.33,112.14 19.44,112.03 arc(19.77,111.53) 19.89,110.95 19.89,85.11 arc(19.69,84.1) 19.12,83.25 13.33,77.46 arc(13.19,77.25) 13.14,77.01 13.14,73.7 arc(13.5,72.85) 14.36,72.49 15.54,72.49 arc(16.11,72.25) 16.34,71.68 16.34,70.57 arc(16.2,70.43) v1(16.06,70.57)
  TOP w0.445: 10.92,150.5 J8.1
  BOTTOM w0.13: C267.1 16.17,68.9 arc(16.3,69.08) 16.34,69.31 16.34,70.57 arc(16.2,70.71) v1(16.06,70.57)
C_CAM12_RIN3_N: length 115.5
  TOP w0.13: v1(19.47,70.57) 19.27,70.77 arc(19.24,70.81) 19.23,70.86 19.23,73.29 arc(19.26,73.43) 19.34,73.55 20.42,74.63 arc(20.88,74.94) 21.42,75.05 22.11,75.05 arc(22.55,75.13) 22.92,75.38 23.09,75.55 arc(23.3,75.86) 23.37,76.22 23.37,85.52 arc(23.19,86.42) 22.68,87.19 arc(22.25,87.83) 22.1,88.59 22.1,111.31 arc(22,111.82) 21.7,112.26 arc(21.23,112.98) 21.06,113.83 21.06,131.84 arc(20.85,132.87) 20.27,133.75 20.02,133.99 arc(19.75,134.39) 19.66,134.87 19.66,169.06 arc(19.42,170.26) 18.74,171.27 17.7,172.31 arc(16.77,172.94) 15.66,173.16 11.05,173.16 10.92,173.29 R1.2
  BOTTOM w0.13: C264.1 19.29,68.96 arc(19.26,69.01) 19.25,69.06 19.25,70.3 arc(19.26,70.35) 19.29,70.39 v1(19.47,70.57)
C_CAM12_RIN3_P: length 121.6
  TOP w0.13: v1(18.5,70.57) 18.67,70.57 arc(18.78,70.62) 18.82,70.73 18.82,73.29 arc(18.88,73.59) 19.05,73.84 20.13,74.92 arc(20.72,75.32) 21.42,75.45 22.11,75.45 arc(22.39,75.51) 22.63,75.67 22.8,75.84 arc(22.92,76.02) 22.96,76.22 22.96,85.52 arc(22.81,86.27) 22.39,86.9 arc(21.87,87.68) 21.69,88.59 21.69,111.31 arc(21.62,111.67) 21.42,111.97 arc(20.85,112.82) 20.65,113.83 20.65,131.84 arc(20.47,132.72) 19.98,133.46 19.74,133.7 arc(19.38,134.24) 19.25,134.87 19.25,169.06 arc(19.04,170.1) 18.45,170.98 17.41,172.02 arc(16.61,172.56) 15.66,172.75 10.92,172.75
  TOP w0.445: 10.92,172.59 J5.1
  BOTTOM w0.13: C265.1 18.42,68.66 18.72,68.96 arc(18.81,69.09) 18.84,69.25 18.84,70.53 arc(18.79,70.65) 18.67,70.7 18.63,70.7 arc(18.54,70.66) v1(18.5,70.57)
C_DOUT_N: length 41.2
  TOP w0.102: v1(42.49,165.52) 42.7,165.31 arc(42.85,165.21) 43.02,165.18 43.74,165.18 arc(44.3,165.29) 44.78,165.61 45.03,165.86 57.45,178.28 arc(58.02,178.66) 58.68,178.79 64.11,178.79 arc(65.28,178.56) 66.28,177.89 68.91,175.26 arc(69.6,174.8) 70.41,174.64 73.67,174.64 arc(73.74,174.67) 73.78,174.74 R222.2
  BOTTOM w0.102: C406.1 40.66,165.4 arc(40.88,165.25) 41.15,165.19 41.99,165.19 arc(42.16,165.23) 42.3,165.32 v1(42.49,165.52)
C_DOUT_P: length 45.6
  TOP w0.102: J21.1 70.41,174.37 arc(69.5,174.55) 68.72,175.07 66.09,177.7 arc(65.18,178.31) 64.11,178.52 58.68,178.52 arc(58.12,178.41) 57.64,178.09 54.6,175.05 44.97,165.42 arc(44.4,165.04) 43.74,164.91 42.97,164.91 arc(42.81,164.88) 42.68,164.79 v1(42.49,164.6)
  BOTTOM w0.102: C405.1 40.65,164.71 arc(40.88,164.87) 41.16,164.93 42.01,164.93 arc(42.16,164.9) 42.28,164.81 v1(42.49,164.6)
C_HUB1_CMLOUT0N: length 4.7
  BOTTOM w0.102: C181.2 21.85,122.97 22.03,123.15 22.47,123.15 22.61,123.01 22.61,122.67 24.01,121.28 24.69,121.28 24.81,121.16 U9.63
C_HUB1_CMLOUT0P: length 4.7
  BOTTOM w0.102: U9.64 24.78,121.66 24.67,121.54 24.12,121.54 22.88,122.78 22.88,123.12 22.58,123.42 22.09,123.42 21.85,123.65 C179.2
C_HUB1_CMLOUT1N: length 7
  BOTTOM w0.102: U9.65 24.8,122.16 24.68,122.28 24.03,122.28 23.63,122.67 23.63,123.87 22.83,124.66 22.83,126.34 22.66,126.52 22.23,126.52 22.06,126.35 C167.2
C_HUB1_CMLOUT1P: length 7
  BOTTOM w0.102: C166.2 22.06,126.91 22.19,126.78 22.77,126.78 23.1,126.45 23.1,124.77 23.9,123.98 23.9,122.79 24.14,122.54 24.68,122.54 24.79,122.66 U9.66
C_HUB1_CMLOUT2N: length 4.8
  BOTTOM w0.102: C178.2 38.8,124.7 38.45,124.7 38.35,124.6 38.35,122.56 38.06,122.28 37.49,122.28 37.37,122.16 U9.2
C_HUB1_CMLOUT2P: length 4.8
  BOTTOM w0.102: U9.1 37.38,122.66 37.5,122.54 37.95,122.54 38.09,122.67 38.09,124.71 38.34,124.97 38.8,124.97 C171.2
C_HUB1_CMLOUT3N: length 3.1
  BOTTOM w0.102: U9.4 37.39,121.16 37.51,121.28 38.06,121.28 38.56,121.77 39.28,121.77 39.4,121.65 C182.2
C_HUB1_CMLOUT3P: length 3.1
  BOTTOM w0.102: C180.2 39.4,122.14 39.3,122.04 38.45,122.04 37.95,121.54 37.48,121.54 37.37,121.66 U9.3
C_HUB2_CMLOUT0N: length 4.8
  BOTTOM w0.102: U24.63 44.83,70.63 44.94,70.75 44.94,72.12 45.9,73.08 45.9,73.97 45.8,74.07 C249.2
C_HUB2_CMLOUT0P: length 4.8
  BOTTOM w0.102: C248.2 46.27,74.07 46.17,73.97 46.17,72.97 45.21,72.01 45.21,70.74 45.33,70.62 U24.64
C_HUB2_CMLOUT1N: length 7.2
  BOTTOM w0.102: U24.65 45.83,70.62 45.94,70.73 45.94,71.16 47.64,72.86 49.59,72.86 49.84,73.1 49.84,73.97 49.73,74.07 C247.2
C_HUB2_CMLOUT1P: length 7.2
  BOTTOM w0.102: U24.66 46.33,70.58 46.21,70.7 46.21,71.05 47.75,72.59 49.7,72.59 50.1,72.99 50.1,73.97 50.2,74.07 C246.2
C_HUB2_CMLOUT2N: length 9.4
  BOTTOM w0.102: C306.2 52.12,54.48 52.22,54.58 52.22,55.02 52.06,55.18 48.1,55.18 45.94,57.33 45.94,57.89 45.83,58 U24.2
C_HUB2_CMLOUT2P: length 9.3
  BOTTOM w0.102: U24.1 46.33,58.01 46.21,57.89 46.21,57.44 48.21,55.45 52.17,55.45 52.49,55.13 52.49,54.59 52.6,54.48 C305.2
C_HUB2_CMLOUT3N: length 5.2
  BOTTOM w0.102: C308.2 46.58,54.48 46.68,54.58 46.68,55.6 44.94,57.33 44.94,57.92 44.83,58.04 U24.4
C_HUB2_CMLOUT3P: length 5.2
  BOTTOM w0.102: C307.2 47.06,54.48 46.95,54.6 46.95,55.71 45.21,57.44 45.21,57.96 45.33,58.08 U24.3
C_HUB3_CMLOUT0N: length 7.2
  BOTTOM w0.102: U25.63 8.78,60.94 8.67,61.05 4.13,61.05 3.64,60.57 3.64,60.03 3.97,59.7 C298.2
C_HUB3_CMLOUT0P: length 7.2
  BOTTOM w0.102: C299.2 2.93,59.7 3.38,60.14 3.38,60.68 4.02,61.32 8.66,61.32 8.78,61.44 U25.64
C_HUB3_CMLOUT1N: length 4.8
  BOTTOM w0.102: U25.65 8.82,61.94 8.71,62.05 7,62.05 6.11,62.94 6.11,63.69 5.69,64.11 C284.2
C_HUB3_CMLOUT1P: length 4.8
  BOTTOM w0.102: C283.2 6.53,64.11 6.37,63.95 6.37,63.05 7.11,62.32 8.7,62.32 8.82,62.44 U25.66
C_HUB3_CMLOUT2N: length 5.3
  BOTTOM w0.102: U25.2 21.4,61.94 21.51,62.05 21.83,62.05 22.72,62.94 22.72,63.54 22.9,63.71 23.69,63.71 24.1,64.12 24.1,64.5 C276.2
C_HUB3_CMLOUT2P: length 5.3
  BOTTOM w0.102: U25.1 21.35,62.44 21.47,62.32 21.72,62.32 22.45,63.05 22.45,63.65 22.79,63.98 23.58,63.98 23.84,64.23 23.84,64.77 23.66,64.94 C277.2
C_HUB3_CMLOUT3N: length 5
  BOTTOM w0.102: C289.2 24.91,62.48 24.81,62.58 23.41,62.58 21.88,61.05 21.5,61.05 21.39,60.94 U25.4
C_HUB3_CMLOUT3P: length 5
  BOTTOM w0.102: C286.2 24.91,62.95 24.81,62.85 23.3,62.85 21.77,61.32 21.51,61.32 21.39,61.44 U25.3
CAM1_RIN_N: length 53.5
  TOP w0.13: R2.2 71.41,154.12 71.28,154.25 55.12,154.25 arc(52.83,153.79) 50.89,152.5 38.53,140.14 arc(36.78,138.96) 34.71,138.55 33.72,138.55 arc(32.8,138.37) 32.03,137.85 28.23,134.05 arc(27.9,133.55) 27.78,132.97 27.78,132.56 arc(27.83,132.44) 27.96,132.38 C132.1
CAM1_RIN_P: length 60.9
  TOP w0.13: C133.1 27.18,132.38 arc(27.31,132.44) 27.37,132.57 27.37,132.97 arc(27.52,133.71) 27.94,134.34 31.74,138.14 arc(32.65,138.75) 33.72,138.96 34.71,138.96 arc(36.62,139.34) 38.24,140.43 50.6,152.78 arc(52.67,154.17) 55.12,154.66 71.41,154.66
  TOP w0.445: 71.41,154.81 J4.1
CAM2_RIN_N: length 42.8
  TOP w0.13: R8.2 71.41,134.56 71.28,134.69 33.35,134.69 arc(32.23,134.47) 31.28,133.83 31.19,133.74 arc(30.96,133.4) 30.88,133.01 30.88,132.5 arc(30.95,132.34) 31.11,132.28 C160.1
CAM2_RIN_P: length 50.2
  TOP w0.13: C161.1 30.26,132.28 arc(30.41,132.34) 30.47,132.5 30.47,133.01 arc(30.58,133.56) 30.9,134.03 30.99,134.12 arc(32.07,134.84) 33.35,135.1 71.41,135.1
  TOP w0.445: 71.41,135.25 J7.1
CAM3_RIN_N: length 40.7
  TOP w0.13: R19.2 71.41,115 71.28,115.13 63.52,115.13 arc(58.57,116.11) 54.38,118.92 43.42,129.87 arc(41.65,131.05) 39.57,131.47 37.65,131.47 arc(37.49,131.4) 37.42,131.24 C198.1
CAM3_RIN_P: length 47.5
  TOP w0.13: C201.1 37.42,132.1 arc(37.49,131.94) 37.64,131.88 39.57,131.88 arc(41.81,131.43) 43.71,130.16 54.67,119.21 arc(58.73,116.49) 63.52,115.54 71.41,115.54
  TOP w0.445: 71.41,115.7 J10.1
CAM4_RIN_N: length 55.2
  TOP w0.13: C223.1 38.69,128.28 arc(38.75,128.42) 38.88,128.48 39.19,128.48 arc(40.55,128.21) 41.7,127.44 51.16,117.98 arc(52.48,116) 52.95,113.66 52.95,103.79 arc(55.35,97.98) 61.16,95.57 71.28,95.57 71.41,95.44 R27.2
CAM4_RIN_P: length 62
  TOP w0.13: 71.41,95.98 61.16,95.98 arc(55.64,98.27) 53.35,103.79 53.35,113.66 arc(52.86,116.16) 51.45,118.27 41.99,127.72 arc(40.71,128.58) 39.19,128.89 38.87,128.89 arc(38.74,128.94) 38.69,129.07 C226.1
  TOP w0.445: 71.41,96.14 J13.1
CAM5_RIN0_N: length 6.8
  BOTTOM w0.13: U24.71 47.12,67.62 47.78,67.62 arc(48.03,67.67) 48.24,67.81 48.68,68.24 arc(48.77,68.31) 48.88,68.33 50.36,68.33 arc(50.65,68.39) 50.89,68.55 51.08,68.74 arc(51.31,69.08) 51.39,69.49 51.39,69.62 arc(51.5,69.86) 51.74,69.96 51.91,69.96 arc(52.08,69.89) 52.15,69.72 arc(52.22,69.55) C262.2
CAM5_RIN0_P: length 6.8
  BOTTOM w0.13: U24.70 47.12,68.03 47.78,68.03 arc(47.87,68.04) 47.95,68.1 48.39,68.53 arc(48.61,68.68) 48.88,68.74 50.36,68.74 arc(50.49,68.76) 50.6,68.84 50.8,69.03 arc(50.94,69.24) 50.99,69.49 50.99,69.62 arc(51.21,70.15) 51.74,70.37 51.92,70.37 arc(52.09,70.44) 52.16,70.6 arc(52.22,70.77) C260.2
CAM6_RIN1_N: length 5.7
  BOTTOM w0.13: U24.74 47.12,66.12 47.96,66.12 arc(48.01,66.11) 48.05,66.08 48.28,65.85 arc(48.45,65.74) 48.66,65.69 51.7,65.69 arc(51.78,65.68) 51.86,65.63 C281.2
CAM6_RIN1_P: length 5.6
  BOTTOM w0.13: C274.2 52.16,66.29 arc(51.94,66.15) 51.7,66.1 48.66,66.1 arc(48.61,66.11) 48.57,66.14 48.34,66.37 arc(48.16,66.49) 47.96,66.53 47.12,66.53 U24.73
CAM7_RIN2_N: length 5.7
  BOTTOM w0.13: C288.2 52.02,62.56 arc(51.9,62.64) 51.76,62.67 arc(51.39,62.6) 51.08,62.39 51.08,62.39 arc(50.78,62.19) 50.43,62.12 47.12,62.12 U24.82
CAM7_RIN2_P: length 5.7
  BOTTOM w0.13: C285.2 51.89,63.13 arc(51.83,63.09) 51.76,63.08 arc(51.24,62.98) 50.79,62.68 50.79,62.68 arc(50.62,62.57) 50.43,62.53 47.12,62.53 U24.81
CAM8_RIN3_N: length 5.7
  BOTTOM w0.13: U24.85 47.12,60.62 49.44,60.62 arc(49.85,60.54) 50.19,60.31 arc(50.72,59.95) 51.34,59.83 51.63,59.83 arc(51.88,59.78) 52.08,59.64 C297.2
CAM8_RIN3_P: length 5.7
  BOTTOM w0.13: U24.84 47.12,61.03 49.44,61.03 arc(50,60.91) 50.48,60.6 arc(50.88,60.33) 51.34,60.24 51.63,60.24 arc(51.84,60.28) 52.02,60.4 C292.2
CAM9_RIN0_N: length 5
  BOTTOM w0.13: C270.2 10.79,67.52 arc(10.66,67.31) 10.61,67.07 10.61,66.38 arc(10.72,65.84) 11.03,65.37 11.54,64.86 arc(11.74,64.57) 11.8,64.23 11.8,63.23 U25.71
CAM9_RIN0_P: length 5.1
  BOTTOM w0.13: C271.2 9.96,67.28 arc(10.14,67.01) 10.2,66.7 10.2,66.38 arc(10.34,65.68) 10.74,65.08 11.25,64.57 arc(11.36,64.41) 11.39,64.23 11.39,63.23 U25.70
CAM10_RIN1_N: length 4.7
  BOTTOM w0.13: U25.74 13.3,63.23 13.3,67.12 arc(13.32,67.23) 13.39,67.32 C268.2
CAM10_RIN1_P: length 4.7
  BOTTOM w0.13: U25.73 12.89,63.23 12.89,67.06 arc(12.88,67.13) 12.85,67.18 C269.2
CAM11_RIN2_N: length 4.8
  BOTTOM w0.13: C266.2 16.97,67.5 arc(16.84,67.31) 16.8,67.08 16.8,64.91 arc(16.84,64.71) 16.95,64.54 17.04,64.45 arc(17.24,64.16) 17.3,63.83 17.3,63.23 U25.82
CAM11_RIN2_P: length 4.8
  BOTTOM w0.13: C267.2 16.29,67.32 arc(16.36,67.21) 16.39,67.08 16.39,64.91 arc(16.46,64.55) 16.66,64.25 16.76,64.16 arc(16.86,64.01) 16.89,63.83 16.89,63.23 U25.81
CAM12_RIN3_N: length 4.8
  BOTTOM w0.13: U25.85 18.8,63.23 18.8,64.43 arc(18.83,64.58) 18.92,64.71 arc(19.11,65) 19.18,65.33 19.18,67.09 arc(19.21,67.25) 19.3,67.39 C264.2
CAM12_RIN3_P: length 4.8
  BOTTOM w0.13: U25.84 18.39,63.23 18.39,64.43 arc(18.45,64.74) 18.63,65 arc(18.73,65.15) 18.77,65.33 18.77,67.09 arc(18.73,67.27) 18.63,67.43 C265.2
CLK_BUF_OE: length 2.6
  BOTTOM w0.152: U22.24 20.09,76.27 20.96,75.4 R167.1
CLK_BUF_SEL: length 1.9
  BOTTOM w0.152: R157.1 20.65,77.72 20.2,77.27 U22.22
CSI0_CLK_N: length 125.5
  TOP w0.102: v1(51.91,27.58) 52.11,27.78 arc(52.18,27.89) 52.21,28.02 52.21,29.47 arc(52.2,29.51) 52.18,29.54 52.12,29.6 arc(52.1,29.63) 52.09,29.67 J2.7
  L03_SIG1 w0.089: v1(51.91,27.58) 52.08,27.41 arc(52.12,27.35) 52.13,27.28 52.13,27.18 arc(52.28,26.83) 52.63,26.68 53.31,26.68 arc(53.61,26.74) 53.86,26.91 55.98,29.03 arc(56.26,29.22) 56.59,29.28 56.82,29.28 arc(57.19,29.36) 57.51,29.57 57.73,29.79 arc(57.95,30.12) 58.03,30.51 58.03,37.39 arc(57.83,37.85) 57.37,38.04 57.03,38.04 arc(56.83,38.13) 56.75,38.33 56.75,38.42 arc(56.82,38.6) 56.99,38.67 57.52,38.67 arc(58.17,39.32) 57.52,39.98 57.07,39.98 arc(56.88,40.06) 56.8,40.25 56.8,40.35 arc(56.87,40.52) 57.04,40.6 57.45,40.6 arc(58.11,41.25) 57.45,41.91 57.01,41.91 arc(56.8,41.99) 56.71,42.21 56.71,42.3 arc(56.78,42.46) 56.93,42.53 57.37,42.53 arc(57.83,42.72) 58.03,43.18 58.03,60.68 arc(57.88,61.42) 57.46,62.05 57.36,62.15 arc(57.13,62.5) 57.05,62.91 57.05,67.39 arc(57.14,67.61) 57.36,67.7 57.72,67.7 arc(58.38,68.36) 57.72,69.01 57.36,69.01 arc(57.14,69.1) 57.05,69.32 57.05,72.37 arc(56.88,73.23) 56.39,73.96 52.31,78.04 arc(52.08,78.38) 52,78.78 52,79.97 arc(52.18,80.4) 52.61,80.57 53.64,80.57 arc(54.19,80.68) 54.66,81 56.51,82.84 arc(56.99,83.57) 57.16,84.43 57.16,85.12 arc(57.32,85.92) 57.78,86.6 57.8,86.62 arc(58.15,87.15) 58.27,87.77 58.27,89.2 arc(58.2,89.58) 57.98,89.91 57.85,90.04 arc(57.78,90.14) 57.76,90.26 57.76,92.78 arc(57.84,92.99) v1(58.05,93.07)
  BOTTOM w0.102: U9.31 32.32,110.83 arc(32.32,110.79) 32.29,110.76 32.24,110.7 arc(32.22,110.67) 32.21,110.63 32.21,108.36 arc(32.56,107.5) 33.42,107.15 36.46,107.15 arc(36.87,107.23) 37.22,107.46 37.46,107.7 arc(37.76,107.9) 38.11,107.97 46.37,107.97 arc(47.08,107.83) 47.68,107.43 53.06,102.04 arc(53.28,101.72) 53.35,101.35 arc(53.57,100.25) 54.19,99.32 56.51,97.01 arc(57.41,95.66) 57.72,94.06 57.72,93.44 arc(57.73,93.4) 57.75,93.37 v1(58.05,93.07)
CSI0_CLK_P: length 125.4
  TOP w0.102: J2.5 52.59,29.67 arc(52.58,29.63) 52.56,29.6 52.5,29.54 arc(52.48,29.51) 52.47,29.47 52.47,27.46 arc(52.52,27.36) 52.62,27.32 arc(52.76,27.38) 52.82,27.53 v1(52.82,27.58)
  L03_SIG1 w0.089: v1(52.82,27.58) 52.77,27.64 arc(52.58,27.67) 52.48,27.51 52.48,27.18 arc(52.52,27.07) 52.63,27.03 53.31,27.03 arc(53.48,27.06) 53.62,27.15 55.74,29.27 arc(56.13,29.53) 56.59,29.63 56.82,29.63 arc(57.06,29.67) 57.27,29.81 57.49,30.03 arc(57.63,30.25) 57.68,30.51 57.68,37.39 arc(57.59,37.61) 57.37,37.7 57.03,37.7 arc(56.59,37.89) 56.4,38.33 56.4,38.42 arc(56.58,38.84) 56.99,39.01 57.52,39.01 arc(57.83,39.32) 57.52,39.63 57.07,39.63 arc(56.63,39.81) 56.45,40.25 56.45,40.35 arc(56.63,40.77) 57.04,40.94 57.45,40.94 arc(57.76,41.25) 57.45,41.56 57.01,41.56 arc(56.56,41.75) 56.37,42.21 56.37,42.3 arc(56.53,42.7) 56.93,42.87 57.37,42.87 arc(57.59,42.96) 57.68,43.18 57.68,60.68 arc(57.56,61.29) 57.22,61.81 57.12,61.9 arc(56.81,62.36) 56.7,62.91 56.7,67.39 arc(56.9,67.86) 57.36,68.05 57.72,68.05 arc(58.04,68.36) 57.72,68.67 57.36,68.67 arc(56.9,68.86) 56.7,69.32 56.7,72.37 arc(56.56,73.1) 56.15,73.71 52.07,77.79 arc(51.76,78.25) 51.66,78.78 51.66,79.97 arc(51.94,80.64) 52.61,80.92 53.64,80.92 arc(54.06,81) 54.42,81.24 56.26,83.08 arc(56.68,83.7) 56.82,84.43 56.82,85.12 arc(57.01,86.05) 57.54,86.84 57.56,86.86 arc(57.83,87.28) 57.93,87.77 57.93,89.2 arc(57.88,89.45) 57.73,89.67 57.61,89.8 arc(57.46,90.01) 57.41,90.26 57.41,92.87 arc(57.35,93.01) 57.21,93.07 v1(57.13,93.07)
  BOTTOM w0.102: U9.32 31.82,110.83 arc(31.83,110.79) 31.85,110.76 31.91,110.7 arc(31.93,110.67) 31.94,110.63 31.94,108.36 arc(32.37,107.31) 33.42,106.88 36.46,106.88 arc(36.97,106.98) 37.41,107.27 37.65,107.51 arc(37.86,107.65) 38.11,107.7 46.37,107.7 arc(46.97,107.58) 47.49,107.24 52.88,101.85 arc(53.03,101.62) 53.09,101.35 arc(53.32,100.15) 54,99.13 56.32,96.82 arc(57.16,95.55) 57.46,94.06 57.46,93.44 arc(57.45,93.4) 57.43,93.37 v1(57.13,93.07)
CSI0_D0_N: length 125.5
  TOP w0.102: v1(50.41,26.71) 50.51,26.8 arc(50.57,26.9) 50.59,27.01 J2.11
  L03_SIG1 w0.089: v1(50.41,26.71) 50.5,26.62 arc(50.6,26.47) 50.63,26.29 50.63,26.15 arc(50.8,25.74) 51.21,25.57 53.62,25.57 arc(54.32,25.71) 54.92,26.11 56.56,27.75 arc(56.88,27.96) 57.25,28.04 57.75,28.04 arc(58.27,28.14) 58.71,28.44 59.04,28.77 arc(59.37,29.26) 59.49,29.84 59.49,44.19 arc(59.55,44.5) 59.73,44.77 59.93,44.98 arc(60.22,45.41) 60.32,45.92 60.32,58.31 arc(60.27,58.58) 60.12,58.81 59.92,59.01 arc(59.79,59.2) 59.75,59.43 59.75,72.33 arc(59.49,73.63) 58.75,74.73 57.56,75.92 arc(56.86,76.96) 56.62,78.19 56.62,80.74 arc(56.7,81.16) 56.94,81.53 58.24,82.83 arc(58.8,83.2) 59.46,83.33 59.85,83.33 arc(60.53,83.47) 61.1,83.85 61.24,83.99 arc(61.59,84.51) 61.71,85.14 61.71,89.36 arc(61.53,90.3) 61,91.09 60.05,92.04 arc(59.68,92.59) 59.55,93.25 59.55,94.06 arc(59.43,94.66) 59.09,95.16 58.75,95.51 arc(58.25,95.84) 57.66,95.96 53.32,95.96 arc(53.09,96) 52.9,96.13 52.82,96.22 arc(52.7,96.39) 52.66,96.59 52.66,96.77 arc(52.75,96.99) v1(52.97,97.08)
  BOTTOM w0.102: v1(52.97,97.08) 52.68,97.37 arc(52.66,97.4) 52.65,97.44 52.65,98.1 arc(52.34,99.65) 51.46,100.96 48.04,104.39 arc(46.9,105.15) 45.54,105.42 32.88,105.42 arc(31.7,105.91) 31.21,107.09 31.21,110.63 arc(31.22,110.67) 31.24,110.7 31.29,110.76 arc(31.32,110.79) 31.32,110.83 U9.33
CSI0_D0_P: length 125.4
  TOP w0.102: v1(51.32,26.71) 51.28,26.66 arc(51.12,26.59) 50.95,26.66 arc(50.88,26.77) 50.86,26.89 50.86,29.24 arc(50.89,29.38) 50.97,29.5 50.98,29.52 arc(51.06,29.64) 51.09,29.78 J2.9
  L03_SIG1 w0.089: v1(51.32,26.71) 51.32,26.77 arc(51.29,26.86) 51.19,26.9 51.11,26.9 arc(51.02,26.86) 50.98,26.77 50.98,26.15 arc(51.04,25.98) 51.21,25.92 53.62,25.92 arc(54.19,26.03) 54.68,26.36 56.32,27.99 arc(56.75,28.28) 57.25,28.38 57.75,28.38 arc(58.14,28.46) 58.47,28.68 58.8,29.01 arc(59.05,29.39) 59.14,29.84 59.14,44.19 arc(59.23,44.64) 59.49,45.02 59.69,45.22 arc(59.91,45.54) 59.98,45.92 59.98,58.31 arc(59.95,58.45) 59.87,58.57 59.68,58.77 arc(59.47,59.07) 59.4,59.43 59.4,72.33 arc(59.17,73.5) 58.51,74.49 57.31,75.68 arc(56.54,76.83) 56.27,78.19 56.27,80.74 arc(56.38,81.3) 56.7,81.77 58,83.07 arc(58.67,83.52) 59.46,83.67 59.85,83.67 arc(60.4,83.78) 60.86,84.09 61,84.23 arc(61.27,84.65) 61.37,85.14 61.37,89.36 arc(61.21,90.17) 60.76,90.85 59.81,91.8 arc(59.36,92.46) 59.21,93.25 59.21,94.06 arc(59.11,94.53) 58.85,94.92 58.5,95.27 arc(58.12,95.53) 57.66,95.62 53.32,95.62 arc(52.96,95.69) 52.66,95.89 52.58,95.97 arc(52.39,96.26) 52.32,96.59 52.32,96.86 arc(52.25,97.01) 52.1,97.08 v1(52.06,97.08)
  BOTTOM w0.102: U9.34 30.82,110.83 arc(30.83,110.79) 30.85,110.76 30.91,110.7 arc(30.93,110.67) 30.94,110.63 30.94,107.09 arc(31.51,105.72) 32.88,105.15 45.54,105.15 arc(46.79,104.91) 47.85,104.2 51.28,100.77 arc(52.09,99.55) 52.38,98.1 52.38,97.44 arc(52.37,97.4) 52.35,97.37 v1(52.06,97.08)
CSI0_D1_N: length 125.2
  TOP w0.102: v1(48.88,28.37) 49,28.48 arc(49.07,28.59) 49.09,28.71 J2.15
  L03_SIG1 w0.089: v1(55.43,94.74) 55.47,94.7 arc(55.5,94.54) 55.37,94.45 53.51,94.45 arc(52.92,94.33) 52.42,94 51.49,93.07 arc(51.2,92.63) 51.1,92.13 51.1,91.89 arc(50.97,91.25) 50.61,90.71 48.16,88.26 arc(47.44,87.17) 47.18,85.89 47.18,79.97 arc(47.44,78.68) 48.17,77.58 52.91,72.84 arc(53.32,72.23) 53.46,71.5 53.46,50.95 arc(53.63,50.11) 54.11,49.39 54.66,48.85 arc(55.03,48.28) 55.16,47.62 55.16,46.84 arc(55.05,46.56) 54.76,46.44 53.57,46.44 arc(52.83,45.7) 53.57,44.95 54.76,44.95 arc(55.05,44.84) 55.16,44.55 55.16,43.7 arc(55,43.31) 54.61,43.15 53.67,43.15 arc(52.77,42.26) 53.67,41.36 54.61,41.36 arc(55,41.2) 55.16,40.81 55.16,37.84 arc(55.05,37.56) 54.76,37.44 54.53,37.44 arc(54,37.22) 53.78,36.7 53.78,36.65 arc(53.98,36.16) 54.47,35.96 54.76,35.96 arc(55.05,35.84) 55.16,35.56 55.16,34.08 arc(55.06,33.53) 54.74,33.07 54.23,32.55 arc(53.87,32.01) 53.74,31.37 53.74,30.1 arc(53.7,29.89) 53.58,29.71 arc(53.23,29.48) 52.82,29.4 49.81,29.4 arc(49.36,29.21) 49.17,28.76 49.17,28.65 arc(49.09,28.45) v1(48.88,28.37)
  BOTTOM w0.102: U9.35 30.32,110.83 arc(30.32,110.79) 30.29,110.76 30.24,110.7 arc(30.22,110.67) 30.21,110.63 30.21,107.13 arc(30.46,105.84) 31.19,104.75 arc(32.5,103.88) 34.03,103.57 41.66,103.57 arc(45.1,102.89) 48.03,100.93 50.48,98.48 arc(50.77,98.05) 50.87,97.54 arc(50.93,97.25) 51.09,97.01 53.06,95.03 arc(53.75,94.57) 54.56,94.41 55.11,94.41 arc(55.34,94.51) v1(55.43,94.74)
CSI0_D1_P: length 125.3
  TOP w0.102: J2.13 49.59,29.78 arc(49.56,29.64) 49.48,29.52 49.47,29.5 arc(49.39,29.38) 49.36,29.24 49.36,28.49 arc(49.4,28.4) 49.48,28.37 v1(49.8,28.37)
  L03_SIG1 w0.089: v1(49.8,28.37) arc(49.6,28.45) 49.51,28.65 49.51,28.76 arc(49.6,28.97) 49.81,29.06 52.82,29.06 arc(53.36,29.16) 53.82,29.47 arc(54.02,29.76) 54.08,30.1 54.08,31.37 arc(54.19,31.88) 54.47,32.31 54.99,32.82 arc(55.37,33.4) 55.51,34.08 55.51,35.56 arc(55.29,36.08) 54.76,36.3 54.47,36.3 arc(54.23,36.4) 54.13,36.65 54.13,36.7 arc(54.24,36.98) 54.53,37.1 54.76,37.1 arc(55.29,37.32) 55.51,37.84 55.51,40.81 arc(55.25,41.44) 54.61,41.7 53.67,41.7 arc(53.12,42.26) 53.67,42.81 54.61,42.81 arc(55.25,43.07) 55.51,43.7 55.51,44.55 arc(55.29,45.08) 54.76,45.3 53.57,45.3 arc(53.17,45.7) 53.57,46.1 54.76,46.1 arc(55.29,46.32) 55.51,46.84 55.51,47.62 arc(55.35,48.41) 54.9,49.09 54.35,49.64 arc(53.95,50.24) 53.81,50.95 53.81,71.5 arc(53.64,72.36) 53.15,73.08 48.41,77.82 arc(47.76,78.81) 47.52,79.97 47.52,85.89 arc(47.75,87.04) 48.41,88.02 50.85,90.47 arc(51.29,91.12) 51.44,91.89 51.44,92.13 arc(51.52,92.5) 51.73,92.82 52.67,93.76 arc(53.05,94.02) 53.51,94.11 55.14,94.11 arc(55.35,94.02) v1(55.43,93.82)
  BOTTOM w0.102: U9.36 29.82,110.83 arc(29.83,110.79) 29.85,110.76 29.91,110.7 arc(29.93,110.67) 29.94,110.63 29.94,107.13 arc(30.22,105.74) 31.01,104.56 arc(32.4,103.63) 34.03,103.31 41.66,103.31 arc(45,102.64) 47.84,100.75 50.29,98.29 arc(50.52,97.95) 50.6,97.54 arc(50.68,97.15) 50.9,96.82 52.88,94.85 arc(53.65,94.33) 54.56,94.15 55.11,94.15 arc(55.34,94.05) v1(55.43,93.82)
CSI0_D2_N: length 125.7
  TOP w0.102: J2.19 47.59,32.35 arc(47.57,32.48) 47.5,32.58 v1(47.38,32.69)
  L03_SIG1 w0.089: v1(50.95,95.61) 51.01,95.55 arc(51.05,95.45) 51.01,95.35 arc(50.98,95.33) 50.95,95.33 50.04,95.33 arc(49.66,95.25) 49.35,95.04 49.11,94.8 arc(48.74,94.25) 48.61,93.6 48.61,91.41 arc(48.53,90.99) 48.28,90.63 46.4,88.75 arc(45.74,87.75) 45.51,86.58 45.51,79.54 arc(45.73,78.42) 46.36,77.46 51.15,72.68 arc(51.75,71.78) 51.96,70.72 51.96,56.23 arc(51.86,55.7) 51.56,55.26 arc(51.33,54.91) 51.25,54.51 51.25,51.96 arc(51.13,51.67) 50.85,51.56 49.62,51.56 arc(48.88,50.81) 49.62,50.07 51.51,50.07 arc(51.91,49.67) 51.51,49.27 49.62,49.27 arc(48.88,48.53) 49.62,47.78 50.85,47.78 arc(51.25,47.38) 50.85,46.98 49.62,46.98 arc(48.88,46.24) 49.62,45.5 50.85,45.5 arc(51.25,45.1) 50.85,44.7 49.62,44.7 arc(48.88,43.95) 49.62,43.21 50.85,43.21 arc(51.13,43.09) 51.25,42.81 51.25,41.84 arc(50.91,40.17) 49.96,38.75 49.93,38.71 arc(49.73,38.41) 49.66,38.06 49.66,37.68 arc(49.92,37.04) 50.56,36.78 51.67,36.78 arc(51.95,36.66) 52.07,36.37 52.07,35.16 arc(51.95,34.87) 51.67,34.75 49.36,34.75 arc(49.15,34.71) 48.98,34.59 47.89,33.51 arc(47.73,33.26) 47.67,32.98 arc(47.59,32.78) v1(47.38,32.69)
  BOTTOM w0.102: U9.39 28.32,110.83 arc(28.32,110.79) 28.29,110.76 28.24,110.7 arc(28.22,110.67) 28.21,110.63 28.21,107.73 arc(28.25,107.52) 28.37,107.34 28.47,107.24 arc(28.79,106.75) 28.91,106.17 28.91,105.47 arc(29,105) 29.27,104.61 30.02,103.85 arc(31.53,102.84) 33.31,102.49 35.06,102.49 arc(36.22,102.26) 37.2,101.6 arc(37.49,101.41) 37.83,101.34 39.81,101.34 arc(40.58,101.19) 41.23,100.75 41.81,100.17 arc(42.38,99.79) 43.05,99.66 46.12,99.66 arc(47.03,99.47) 47.8,98.96 48.88,97.88 arc(49.23,97.36) 49.35,96.75 49.35,96.64 arc(49.39,96.4) 49.53,96.2 50.28,95.44 arc(50.46,95.32) 50.67,95.28 50.93,95.28 arc(51.04,95.33) 51.08,95.43 51.08,95.48 arc(51.05,95.57) 50.95,95.61 v1(50.95,95.61)
